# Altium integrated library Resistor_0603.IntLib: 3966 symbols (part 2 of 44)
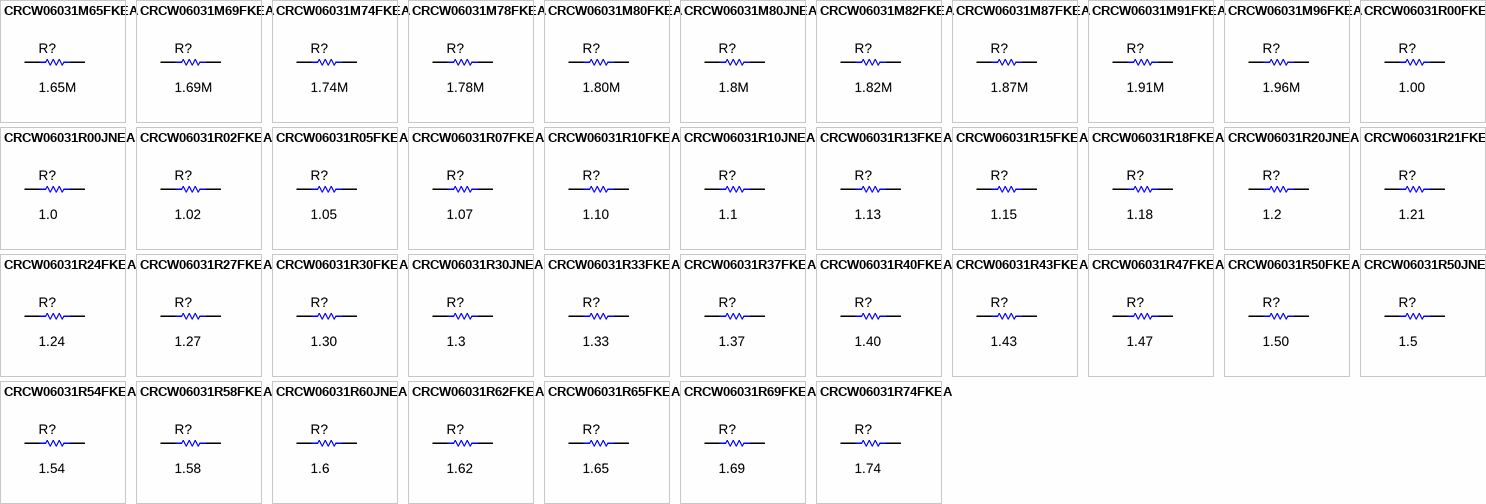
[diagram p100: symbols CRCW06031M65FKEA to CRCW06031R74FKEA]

## CRCW06031M87FKEA
designator R?  ValueDisplayed: 1.87M  (hidden comment: CRCW06031M87FKEA)
RES, 1.87 M, 1%, 0.1 W, 0603; Manufacturer: Vishay-Dale; CompType: Resistor; Value: 1.87Meg; Res_ohm: 1870000; Value_Code: 1M87; Tolerance_%: 1; Power_W: 0.1; Value2: 0.1W; VDC_V: 75; TempCo: 100 ppm/C; SizeArea_mm2: 1.28; SizeX_mm: 1.6; SizeY_mm: 0.8; EIA_Code: E96; U/M: EA; AEC Category: Q200
signal-integrity model Resistor
simulation model Resistor
footprint 0603
footprint 0603M
footprint 0603L
footprint 0603_HV
footprint 0603S
pins: 1, 2

## CRCW06031M91FKEA
designator R?  ValueDisplayed: 1.91M  (hidden comment: CRCW06031M91FKEA)
RES, 1.91 M, 1%, 0.1 W, 0603; Manufacturer: Vishay-Dale; CompType: Resistor; Value: 1.91Meg; Res_ohm: 1910000; Value_Code: 1M91; Tolerance_%: 1; Power_W: 0.1; Value2: 0.1W; VDC_V: 75; TempCo: 100 ppm/C; SizeArea_mm2: 1.28; SizeX_mm: 1.6; SizeY_mm: 0.8; EIA_Code: E96; U/M: EA; AEC Category: Q200
signal-integrity model Resistor
simulation model Resistor
footprint 0603
footprint 0603M
footprint 0603L
footprint 0603_HV
footprint 0603S
pins: 1, 2

## CRCW06031M96FKEA
designator R?  ValueDisplayed: 1.96M  (hidden comment: CRCW06031M96FKEA)
RES, 1.96 M, 1%, 0.1 W, 0603; Manufacturer: Vishay-Dale; CompType: Resistor; Value: 1.96Meg; Res_ohm: 1960000; Value_Code: 1M96; Tolerance_%: 1; Power_W: 0.1; Value2: 0.1W; VDC_V: 75; TempCo: 100 ppm/C; SizeArea_mm2: 1.28; SizeX_mm: 1.6; SizeY_mm: 0.8; EIA_Code: E96; U/M: EA; AEC Category: Q200
signal-integrity model Resistor
simulation model Resistor
footprint 0603
footprint 0603M
footprint 0603L
footprint 0603_HV
footprint 0603S
pins: 1, 2

## CRCW06031R00FKEA
designator R?  ValueDisplayed: 1.00  (hidden comment: CRCW06031R00FKEA)
RES, 1.00, 1%, 0.1 W, 0603; Manufacturer: Vishay-Dale; CompType: Resistor; Value: 1.00; Res_ohm: 1; Value_Code: 1R00; Power_W: 0.1; Value2: 0.1W; VDC_V: 75; TempCo: 100 ppm/C; SizeArea_mm2: 1.28; SizeX_mm: 1.6; SizeY_mm: 0.8; EIA_Code: E96; U/M: EA; AEC Category: Q200; Green_Lifecycle: Active; Green_REACh: Passed
signal-integrity model Resistor
simulation model Resistor
footprint 0603
footprint 0603M
footprint 0603L
footprint 0603_HV
footprint 0603S
pins: 1, 2

## CRCW06031R00JNEA
designator R?  ValueDisplayed: 1.0  (hidden comment: CRCW06031R00JNEA)
RES, 1.0, 5%, 0.1 W, 0603; Manufacturer: Vishay-Dale; CompType: Resistor; Value: 1.0; Res_ohm: 1; Value_Code: 1R00; Tolerance_%: 5; Power_W: 0.1; Value2: 0.1W; VDC_V: 75; TempCo: 200 ppm/C; SizeArea_mm2: 1.28; SizeX_mm: 1.6; SizeY_mm: 0.8; EIA_Code: E24; U/M: EA; AEC Category: Q200; Green_Lifecycle: Active; Green_REACh: Passed
signal-integrity model Resistor
simulation model Resistor
footprint 0603
footprint 0603M
footprint 0603L
footprint 0603_HV
footprint 0603S
pins: 1, 2

## CRCW06031R02FKEA
designator R?  ValueDisplayed: 1.02  (hidden comment: CRCW06031R02FKEA)
RES, 1.02, 1%, 0.1 W, 0603; Manufacturer: Vishay-Dale; CompType: Resistor; Value: 1.02; Value_Code: 1R02; Tolerance_%: 1; Power_W: 0.1; Value2: 0.1W; VDC_V: 75; TempCo: 100 ppm/C; SizeArea_mm2: 1.28; SizeX_mm: 1.6; SizeY_mm: 0.8; EIA_Code: E96; U/M: EA; AEC Category: Q200
signal-integrity model Resistor
simulation model Resistor
footprint 0603
footprint 0603M
footprint 0603L
footprint 0603_HV
footprint 0603S
pins: 1, 2

## CRCW06031R05FKEA
designator R?  ValueDisplayed: 1.05  (hidden comment: CRCW06031R05FKEA)
RES, 1.05, 1%, 0.1 W, 0603; Manufacturer: Vishay-Dale; CompType: Resistor; Value: 1.05; Value_Code: 1R05; Tolerance_%: 1; Power_W: 0.1; Value2: 0.1W; VDC_V: 75; TempCo: 100 ppm/C; SizeArea_mm2: 1.28; SizeX_mm: 1.6; SizeY_mm: 0.8; EIA_Code: E96; U/M: EA; AEC Category: Q200
signal-integrity model Resistor
simulation model Resistor
footprint 0603
footprint 0603M
footprint 0603L
footprint 0603_HV
footprint 0603S
pins: 1, 2

## CRCW06031R07FKEA
designator R?  ValueDisplayed: 1.07  (hidden comment: CRCW06031R07FKEA)
RES, 1.07, 1%, 0.1 W, 0603; Manufacturer: Vishay-Dale; CompType: Resistor; Value: 1.07; Value_Code: 1R07; Tolerance_%: 1; Power_W: 0.1; Value2: 0.1W; VDC_V: 75; TempCo: 100 ppm/C; SizeArea_mm2: 1.28; SizeX_mm: 1.6; SizeY_mm: 0.8; EIA_Code: E96; U/M: EA; AEC Category: Q200
signal-integrity model Resistor
simulation model Resistor
footprint 0603
footprint 0603M
footprint 0603L
footprint 0603_HV
footprint 0603S
pins: 1, 2

## CRCW06031R10FKEA
designator R?  ValueDisplayed: 1.10  (hidden comment: CRCW06031R10FKEA)
RES, 1.10, 1%, 0.1 W, 0603; Manufacturer: Vishay-Dale; CompType: Resistor; Value: 1.10; Res_ohm: 1.1; Value_Code: 1R10; Tolerance_%: 1; Power_W: 0.1; Value2: 0.1W; VDC_V: 75; TempCo: 100 ppm/C; SizeArea_mm2: 1.28; SizeX_mm: 1.6; SizeY_mm: 0.8; EIA_Code: E96; U/M: EA; AEC Category: Q200
signal-integrity model Resistor
simulation model Resistor
footprint 0603
footprint 0603M
footprint 0603L
footprint 0603_HV
footprint 0603S
pins: 1, 2

## CRCW06031R10JNEA
designator R?  ValueDisplayed: 1.1  (hidden comment: CRCW06031R10JNEA)
RES, 1.1, 5%, 0.1 W, 0603; Manufacturer: Vishay-Dale; CompType: Resistor; Value: 1.1; Value_Code: 1R10; Tolerance_%: 5; Power_W: 0.1; Value2: 0.1W; VDC_V: 75; TempCo: 200 ppm/C; SizeArea_mm2: 1.28; SizeX_mm: 1.6; SizeY_mm: 0.8; SizeZ_mm: 1; EIA_Code: E24; U/M: EA; AEC Category: Q200; Green_Lifecycle: Active; Green_REACh: Passed
signal-integrity model Resistor
simulation model Resistor
footprint 0603
footprint 0603M
footprint 0603L
footprint 0603_HV
footprint 0603S
pins: 1, 2

## CRCW06031R13FKEA
designator R?  ValueDisplayed: 1.13  (hidden comment: CRCW06031R13FKEA)
RES, 1.13, 1%, 0.1 W, 0603; Manufacturer: Vishay-Dale; CompType: Resistor; Value: 1.13; Value_Code: 1R13; Tolerance_%: 1; Power_W: 0.1; Value2: 0.1W; VDC_V: 75; TempCo: 100 ppm/C; SizeArea_mm2: 1.28; SizeX_mm: 1.6; SizeY_mm: 0.8; EIA_Code: E96; U/M: EA; AEC Category: Q200
signal-integrity model Resistor
simulation model Resistor
footprint 0603
footprint 0603M
footprint 0603L
footprint 0603_HV
footprint 0603S
pins: 1, 2

## CRCW06031R15FKEA
designator R?  ValueDisplayed: 1.15  (hidden comment: CRCW06031R15FKEA)
RES, 1.15, 1%, 0.1 W, 0603; Manufacturer: Vishay-Dale; CompType: Resistor; Value: 1.15; Value_Code: 1R15; Tolerance_%: 1; Power_W: 0.1; Value2: 0.1W; VDC_V: 75; TempCo: 100 ppm/C; SizeArea_mm2: 1.28; SizeX_mm: 1.6; SizeY_mm: 0.8; EIA_Code: E96; U/M: EA; AEC Category: Q200
signal-integrity model Resistor
simulation model Resistor
footprint 0603
footprint 0603M
footprint 0603L
footprint 0603_HV
footprint 0603S
pins: 1, 2

## CRCW06031R18FKEA
designator R?  ValueDisplayed: 1.18  (hidden comment: CRCW06031R18FKEA)
RES, 1.18, 1%, 0.1 W, 0603; Manufacturer: Vishay-Dale; CompType: Resistor; Value: 1.18; Value_Code: 1R18; Tolerance_%: 1; Power_W: 0.1; Value2: 0.1W; VDC_V: 75; TempCo: 100 ppm/C; SizeArea_mm2: 1.28; SizeX_mm: 1.6; SizeY_mm: 0.8; EIA_Code: E96; U/M: EA; AEC Category: Q200
signal-integrity model Resistor
simulation model Resistor
footprint 0603
footprint 0603M
footprint 0603L
footprint 0603_HV
footprint 0603S
pins: 1, 2

## CRCW06031R20JNEA
designator R?  ValueDisplayed: 1.2  (hidden comment: CRCW06031R20JNEA)
RES, 1.2, 5%, 0.1 W, 0603; Manufacturer: Vishay-Dale; CompType: Resistor; Value: 1.2; Value_Code: 1R20; Tolerance_%: 5; Power_W: 0.1; Value2: 0.1W; VDC_V: 75; TempCo: 200 ppm/C; SizeArea_mm2: 1.28; SizeX_mm: 1.6; SizeY_mm: 0.8; SizeZ_mm: 1; EIA_Code: E24; U/M: EA; AEC Category: Q200
signal-integrity model Resistor
simulation model Resistor
footprint 0603
footprint 0603M
footprint 0603L
footprint 0603_HV
footprint 0603S
pins: 1, 2

## CRCW06031R21FKEA
designator R?  ValueDisplayed: 1.21  (hidden comment: CRCW06031R21FKEA)
RES, 1.21, 1%, 0.1 W, 0603; Manufacturer: Vishay-Dale; CompType: Resistor; Value: 1.21; Value_Code: 1R21; Tolerance_%: 1; Power_W: 0.1; Value2: 0.1W; VDC_V: 75; TempCo: 100 ppm/C; SizeArea_mm2: 1.28; SizeX_mm: 1.6; SizeY_mm: 0.8; EIA_Code: E96; U/M: EA; AEC Category: Q200
signal-integrity model Resistor
simulation model Resistor
footprint 0603
footprint 0603M
footprint 0603L
footprint 0603_HV
footprint 0603S
pins: 1, 2

## CRCW06031R24FKEA
designator R?  ValueDisplayed: 1.24  (hidden comment: CRCW06031R24FKEA)
RES, 1.24, 1%, 0.1 W, 0603; Manufacturer: Vishay-Dale; CompType: Resistor; Value: 1.24; Value_Code: 1R24; Tolerance_%: 1; Power_W: 0.1; Value2: 0.1W; VDC_V: 75; TempCo: 100 ppm/C; SizeArea_mm2: 1.28; SizeX_mm: 1.6; SizeY_mm: 0.8; EIA_Code: E96; U/M: EA; AEC Category: Q200
signal-integrity model Resistor
simulation model Resistor
footprint 0603
footprint 0603M
footprint 0603L
footprint 0603_HV
footprint 0603S
pins: 1, 2

## CRCW06031R27FKEA
designator R?  ValueDisplayed: 1.27  (hidden comment: CRCW06031R27FKEA)
RES, 1.27, 1%, 0.1 W, 0603; Manufacturer: Vishay-Dale; CompType: Resistor; Value: 1.27; Value_Code: 1R27; Tolerance_%: 1; Power_W: 0.1; Value2: 0.1W; VDC_V: 75; TempCo: 100 ppm/C; SizeArea_mm2: 1.28; SizeX_mm: 1.6; SizeY_mm: 0.8; EIA_Code: E96; U/M: EA; AEC Category: Q200
signal-integrity model Resistor
simulation model Resistor
footprint 0603
footprint 0603M
footprint 0603L
footprint 0603_HV
footprint 0603S
pins: 1, 2

## CRCW06031R30FKEA
designator R?  ValueDisplayed: 1.30  (hidden comment: CRCW06031R30FKEA)
RES, 1.30, 1%, 0.1 W, 0603; Manufacturer: Vishay-Dale; CompType: Resistor; Value: 1.30; Res_ohm: 1.3; Value_Code: 1R30; Tolerance_%: 1; Power_W: 0.1; Value2: 0.1W; VDC_V: 75; TempCo: 100 ppm/C; SizeArea_mm2: 1.28; SizeX_mm: 1.6; SizeY_mm: 0.8; EIA_Code: E96; U/M: EA; AEC Category: Q200
signal-integrity model Resistor
simulation model Resistor
footprint 0603
footprint 0603M
footprint 0603L
footprint 0603_HV
footprint 0603S
pins: 1, 2

## CRCW06031R30JNEA
designator R?  ValueDisplayed: 1.3  (hidden comment: CRCW06031R30JNEA)
RES, 1.3, 5%, 0.1 W, 0603; Manufacturer: Vishay-Dale; CompType: Resistor; Value: 1.3; Value_Code: 1R30; Tolerance_%: 5; Power_W: 0.1; Value2: 0.1W; VDC_V: 75; TempCo: 200 ppm/C; SizeArea_mm2: 1.28; SizeX_mm: 1.6; SizeY_mm: 0.8; SizeZ_mm: 1; EIA_Code: E24; U/M: EA; AEC Category: Q200
signal-integrity model Resistor
simulation model Resistor
footprint 0603
footprint 0603M
footprint 0603L
footprint 0603_HV
footprint 0603S
pins: 1, 2

## CRCW06031R33FKEA
designator R?  ValueDisplayed: 1.33  (hidden comment: CRCW06031R33FKEA)
RES, 1.33, 1%, 0.1 W, 0603; Manufacturer: Vishay-Dale; CompType: Resistor; Value: 1.33; Value_Code: 1R33; Tolerance_%: 1; Power_W: 0.1; Value2: 0.1W; VDC_V: 75; TempCo: 100 ppm/C; SizeArea_mm2: 1.28; SizeX_mm: 1.6; SizeY_mm: 0.8; EIA_Code: E96; U/M: EA; AEC Category: Q200
signal-integrity model Resistor
simulation model Resistor
footprint 0603
footprint 0603M
footprint 0603L
footprint 0603_HV
footprint 0603S
pins: 1, 2

## CRCW06031R37FKEA
designator R?  ValueDisplayed: 1.37  (hidden comment: CRCW06031R37FKEA)
RES, 1.37, 1%, 0.1 W, 0603; Manufacturer: Vishay-Dale; CompType: Resistor; Value: 1.37; Value_Code: 1R37; Tolerance_%: 1; Power_W: 0.1; Value2: 0.1W; VDC_V: 75; TempCo: 100 ppm/C; SizeArea_mm2: 1.28; SizeX_mm: 1.6; SizeY_mm: 0.8; EIA_Code: E96; U/M: EA; AEC Category: Q200
signal-integrity model Resistor
simulation model Resistor
footprint 0603
footprint 0603M
footprint 0603L
footprint 0603_HV
footprint 0603S
pins: 1, 2

## CRCW06031R40FKEA
designator R?  ValueDisplayed: 1.40  (hidden comment: CRCW06031R40FKEA)
RES, 1.40, 1%, 0.1 W, 0603; Manufacturer: Vishay-Dale; CompType: Resistor; Value: 1.40; Res_ohm: 1.4; Value_Code: 1R40; Tolerance_%: 1; Power_W: 0.1; Value2: 0.1W; VDC_V: 75; TempCo: 100 ppm/C; SizeArea_mm2: 1.28; SizeX_mm: 1.6; SizeY_mm: 0.8; EIA_Code: E96; U/M: EA; AEC Category: Q200
signal-integrity model Resistor
simulation model Resistor
footprint 0603
footprint 0603M
footprint 0603L
footprint 0603_HV
footprint 0603S
pins: 1, 2

## CRCW06031R43FKEA
designator R?  ValueDisplayed: 1.43  (hidden comment: CRCW06031R43FKEA)
RES, 1.43, 1%, 0.1 W, 0603; Manufacturer: Vishay-Dale; CompType: Resistor; Value: 1.43; Value_Code: 1R43; Tolerance_%: 1; Power_W: 0.1; Value2: 0.1W; VDC_V: 75; TempCo: 100 ppm/C; SizeArea_mm2: 1.28; SizeX_mm: 1.6; SizeY_mm: 0.8; EIA_Code: E96; U/M: EA; AEC Category: Q200
signal-integrity model Resistor
simulation model Resistor
footprint 0603
footprint 0603M
footprint 0603L
footprint 0603_HV
footprint 0603S
pins: 1, 2

## CRCW06031R47FKEA
designator R?  ValueDisplayed: 1.47  (hidden comment: CRCW06031R47FKEA)
RES, 1.47, 1%, 0.1 W, 0603; Manufacturer: Vishay-Dale; CompType: Resistor; Value: 1.47; Value_Code: 1R47; Tolerance_%: 1; Power_W: 0.1; Value2: 0.1W; VDC_V: 75; TempCo: 100 ppm/C; SizeArea_mm2: 1.28; SizeX_mm: 1.6; SizeY_mm: 0.8; EIA_Code: E96; U/M: EA; AEC Category: Q200
signal-integrity model Resistor
simulation model Resistor
footprint 0603
footprint 0603M
footprint 0603L
footprint 0603_HV
footprint 0603S
pins: 1, 2

## CRCW06031R50FKEA
designator R?  ValueDisplayed: 1.50  (hidden comment: CRCW06031R50FKEA)
RES, 1.50, 1%, 0.1 W, 0603; Manufacturer: Vishay-Dale; CompType: Resistor; Value: 1.50; Res_ohm: 1.5; Value_Code: 1R50; Tolerance_%: 1; Power_W: 0.1; Value2: 0.1W; VDC_V: 75; TempCo: 100 ppm/C; SizeArea_mm2: 1.28; SizeX_mm: 1.6; SizeY_mm: 0.8; EIA_Code: E96; U/M: EA; AEC Category: Q200; Green_Lifecycle: Active; Green_REACh: Passed
signal-integrity model Resistor
simulation model Resistor
footprint 0603
footprint 0603M
footprint 0603L
footprint 0603_HV
footprint 0603S
pins: 1, 2

## CRCW06031R50JNEA
designator R?  ValueDisplayed: 1.5  (hidden comment: CRCW06031R50JNEA)
RES, 1.5, 5%, 0.1 W, 0603; Manufacturer: Vishay-Dale; CompType: Resistor; Value: 1.5; Value_Code: 1R50; Tolerance_%: 5; Power_W: 0.1; Value2: 0.1W; VDC_V: 75; TempCo: 200 ppm/C; SizeArea_mm2: 1.28; SizeX_mm: 1.6; SizeY_mm: 0.8; SizeZ_mm: 1; EIA_Code: E24; U/M: EA; AEC Category: Q200
signal-integrity model Resistor
simulation model Resistor
footprint 0603
footprint 0603M
footprint 0603L
footprint 0603_HV
footprint 0603S
pins: 1, 2

## CRCW06031R54FKEA
designator R?  ValueDisplayed: 1.54  (hidden comment: CRCW06031R54FKEA)
RES, 1.54, 1%, 0.1 W, 0603; Manufacturer: Vishay-Dale; CompType: Resistor; Value: 1.54; Value_Code: 1R54; Tolerance_%: 1; Power_W: 0.1; Value2: 0.1W; VDC_V: 75; TempCo: 100 ppm/C; SizeArea_mm2: 1.28; SizeX_mm: 1.6; SizeY_mm: 0.8; EIA_Code: E96; U/M: EA; AEC Category: Q200
signal-integrity model Resistor
simulation model Resistor
footprint 0603
footprint 0603M
footprint 0603L
footprint 0603_HV
footprint 0603S
pins: 1, 2

## CRCW06031R58FKEA
designator R?  ValueDisplayed: 1.58  (hidden comment: CRCW06031R58FKEA)
RES, 1.58, 1%, 0.1 W, 0603; Manufacturer: Vishay-Dale; CompType: Resistor; Value: 1.58; Value_Code: 1R58; Tolerance_%: 1; Power_W: 0.1; Value2: 0.1W; VDC_V: 75; TempCo: 100 ppm/C; SizeArea_mm2: 1.28; SizeX_mm: 1.6; SizeY_mm: 0.8; EIA_Code: E96; U/M: EA; AEC Category: Q200
signal-integrity model Resistor
simulation model Resistor
footprint 0603
footprint 0603M
footprint 0603L
footprint 0603_HV
footprint 0603S
pins: 1, 2

## CRCW06031R60JNEA
designator R?  ValueDisplayed: 1.6  (hidden comment: CRCW06031R60JNEA)
RES, 1.6, 5%, 0.1 W, 0603; Manufacturer: Vishay-Dale; CompType: Resistor; Value: 1.6; Value_Code: 1R60; Tolerance_%: 5; Power_W: 0.1; Value2: 0.1W; VDC_V: 75; TempCo: 200 ppm/C; SizeArea_mm2: 1.28; SizeY_mm: 0.8; SizeZ_mm: 1; EIA_Code: E24; U/M: EA; AEC Category: Q200
signal-integrity model Resistor
simulation model Resistor
footprint 0603
footprint 0603M
footprint 0603L
footprint 0603_HV
footprint 0603S
pins: 1, 2

## CRCW06031R62FKEA
designator R?  ValueDisplayed: 1.62  (hidden comment: CRCW06031R62FKEA)
RES, 1.62, 1%, 0.1 W, 0603; Manufacturer: Vishay-Dale; CompType: Resistor; Value: 1.62; Value_Code: 1R62; Tolerance_%: 1; Power_W: 0.1; Value2: 0.1W; VDC_V: 75; TempCo: 100 ppm/C; SizeArea_mm2: 1.28; SizeX_mm: 1.6; SizeY_mm: 0.8; EIA_Code: E96; U/M: EA; AEC Category: Q200
signal-integrity model Resistor
simulation model Resistor
footprint 0603
footprint 0603M
footprint 0603L
footprint 0603_HV
footprint 0603S
pins: 1, 2

## CRCW06031R65FKEA
designator R?  ValueDisplayed: 1.65  (hidden comment: CRCW06031R65FKEA)
RES, 1.65, 1%, 0.1 W, 0603; Manufacturer: Vishay-Dale; CompType: Resistor; Value: 1.65; Value_Code: 1R65; Tolerance_%: 1; Power_W: 0.1; Value2: 0.1W; VDC_V: 75; TempCo: 100 ppm/C; SizeArea_mm2: 1.28; SizeX_mm: 1.6; SizeY_mm: 0.8; EIA_Code: E96; U/M: EA; AEC Category: Q200
signal-integrity model Resistor
simulation model Resistor
footprint 0603
footprint 0603M
footprint 0603L
footprint 0603_HV
footprint 0603S
pins: 1, 2

## CRCW06031R69FKEA
designator R?  ValueDisplayed: 1.69  (hidden comment: CRCW06031R69FKEA)
RES, 1.69, 1%, 0.1 W, 0603; Manufacturer: Vishay-Dale; CompType: Resistor; Value: 1.69; Value_Code: 1R69; Tolerance_%: 1; Power_W: 0.1; Value2: 0.1W; VDC_V: 75; TempCo: 100 ppm/C; SizeArea_mm2: 1.28; SizeX_mm: 1.6; SizeY_mm: 0.8; EIA_Code: E96; U/M: EA; AEC Category: Q200
signal-integrity model Resistor
simulation model Resistor
footprint 0603
footprint 0603M
footprint 0603L
footprint 0603_HV
footprint 0603S
pins: 1, 2

## CRCW06031R74FKEA
designator R?  ValueDisplayed: 1.74  (hidden comment: CRCW06031R74FKEA)
RES, 1.74, 1%, 0.1 W, 0603; Manufacturer: Vishay-Dale; CompType: Resistor; Value: 1.74; Value_Code: 1R74; Tolerance_%: 1; Power_W: 0.1; Value2: 0.1W; VDC_V: 75; TempCo: 100 ppm/C; SizeArea_mm2: 1.28; SizeX_mm: 1.6; SizeY_mm: 0.8; EIA_Code: E96; U/M: EA; AEC Category: Q200
signal-integrity model Resistor
simulation model Resistor
footprint 0603
footprint 0603M
footprint 0603L
footprint 0603_HV
footprint 0603S
pins: 1, 2

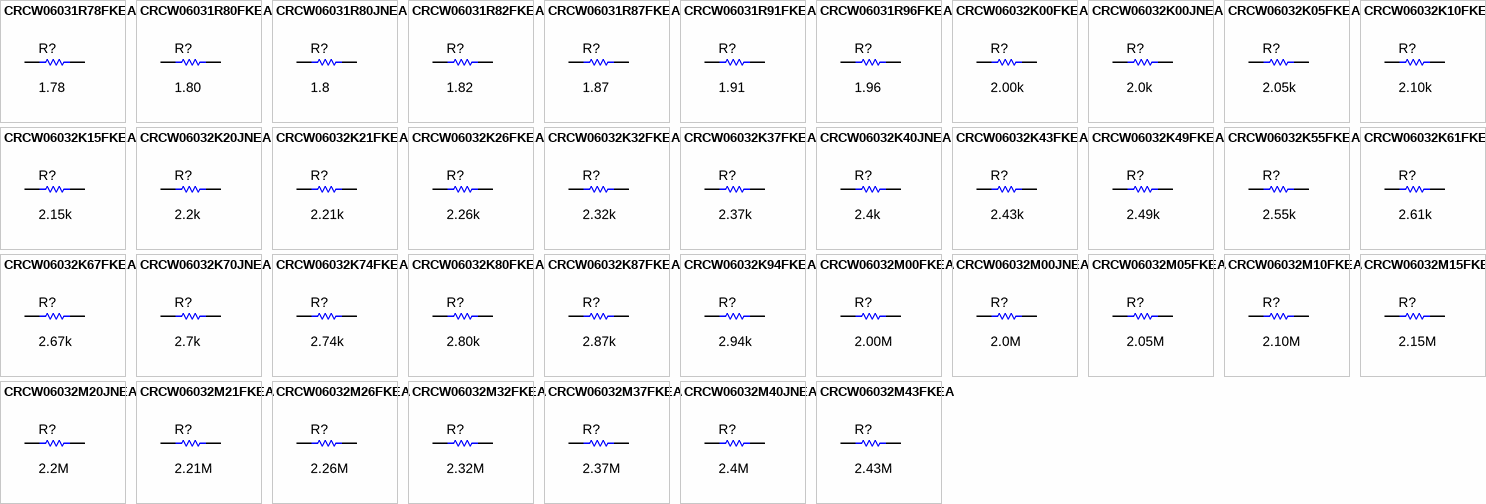
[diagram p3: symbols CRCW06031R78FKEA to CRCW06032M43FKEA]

## CRCW06031R78FKEA
designator R?  ValueDisplayed: 1.78  (hidden comment: CRCW06031R78FKEA)
RES, 1.78, 1%, 0.1 W, 0603; Manufacturer: Vishay-Dale; CompType: Resistor; Value: 1.78; Value_Code: 1R78; Tolerance_%: 1; Power_W: 0.1; Value2: 0.1W; VDC_V: 75; TempCo: 100 ppm/C; SizeArea_mm2: 1.28; SizeX_mm: 1.6; SizeY_mm: 0.8; EIA_Code: E96; U/M: EA; AEC Category: Q200
signal-integrity model Resistor
simulation model Resistor
footprint 0603
footprint 0603M
footprint 0603L
footprint 0603_HV
footprint 0603S
pins: 1, 2

## CRCW06031R80FKEA
designator R?  ValueDisplayed: 1.80  (hidden comment: CRCW06031R80FKEA)
RES, 1.80, 1%, 0.1 W, AEC-Q200 Grade 0, 0603; Manufacturer: Vishay-Dale; CompType: Resistor; Value: 1.80; Res_ohm: 1.8; Value_Code: 1R80; Tolerance_%: 1; Power_W: 0.1; Value2: 0.1W; TempCo: 100 ppm/C; SizeArea_mm2: 1.28; SizeX_mm: 1.6; SizeY_mm: 0.8; U/M: EA; AEC Category: Q200; AEC Qualified: Y; AEC Grade: 0
signal-integrity model Resistor
simulation model Resistor
footprint 0603
footprint 0603M
footprint 0603L
footprint 0603_HV
footprint 0603S
pins: 1, 2

## CRCW06031R80JNEA
designator R?  ValueDisplayed: 1.8  (hidden comment: CRCW06031R80JNEA)
RES, 1.8, 5%, 0.1 W, 0603; Manufacturer: Vishay-Dale; CompType: Resistor; Value: 1.8; Value_Code: 1R80; Tolerance_%: 5; Power_W: 0.1; Value2: 0.1W; VDC_V: 75; TempCo: 200 ppm/C; SizeArea_mm2: 1.28; SizeX_mm: 1.6; SizeY_mm: 0.8; SizeZ_mm: 1; EIA_Code: E24; U/M: EA; AEC Category: Q200
signal-integrity model Resistor
simulation model Resistor
footprint 0603
footprint 0603M
footprint 0603L
footprint 0603_HV
footprint 0603S
pins: 1, 2

## CRCW06031R82FKEA
designator R?  ValueDisplayed: 1.82  (hidden comment: CRCW06031R82FKEA)
RES, 1.82, 1%, 0.1 W, 0603; Manufacturer: Vishay-Dale; CompType: Resistor; Value: 1.82; Value_Code: 1R82; Tolerance_%: 1; Power_W: 0.1; Value2: 0.1W; VDC_V: 75; TempCo: 100 ppm/C; SizeArea_mm2: 1.28; SizeX_mm: 1.6; SizeY_mm: 0.8; EIA_Code: E96; U/M: EA; AEC Category: Q200
signal-integrity model Resistor
simulation model Resistor
footprint 0603
footprint 0603M
footprint 0603L
footprint 0603_HV
footprint 0603S
pins: 1, 2

## CRCW06031R87FKEA
designator R?  ValueDisplayed: 1.87  (hidden comment: CRCW06031R87FKEA)
RES, 1.87, 1%, 0.1 W, 0603; Manufacturer: Vishay-Dale; CompType: Resistor; Value: 1.87; Value_Code: 1R87; Tolerance_%: 1; Power_W: 0.1; Value2: 0.1W; VDC_V: 75; TempCo: 100 ppm/C; SizeArea_mm2: 1.28; SizeX_mm: 1.6; SizeY_mm: 0.8; EIA_Code: E96; U/M: EA; AEC Category: Q200
signal-integrity model Resistor
simulation model Resistor
footprint 0603
footprint 0603M
footprint 0603L
footprint 0603_HV
footprint 0603S
pins: 1, 2

## CRCW06031R91FKEA
designator R?  ValueDisplayed: 1.91  (hidden comment: CRCW06031R91FKEA)
RES, 1.91, 1%, 0.1 W, 0603; Manufacturer: Vishay-Dale; CompType: Resistor; Value: 1.91; Value_Code: 1R91; Tolerance_%: 1; Power_W: 0.1; Value2: 0.1W; VDC_V: 75; TempCo: 100 ppm/C; SizeArea_mm2: 1.28; SizeX_mm: 1.6; SizeY_mm: 0.8; EIA_Code: E96; U/M: EA; AEC Category: Q200
signal-integrity model Resistor
simulation model Resistor
footprint 0603
footprint 0603M
footprint 0603L
footprint 0603_HV
footprint 0603S
pins: 1, 2

## CRCW06031R96FKEA
designator R?  ValueDisplayed: 1.96  (hidden comment: CRCW06031R96FKEA)
RES, 1.96, 1%, 0.1 W, 0603; Manufacturer: Vishay-Dale; CompType: Resistor; Value: 1.96; Value_Code: 1R96; Tolerance_%: 1; Power_W: 0.1; Value2: 0.1W; VDC_V: 75; TempCo: 100 ppm/C; SizeArea_mm2: 1.28; SizeX_mm: 1.6; SizeY_mm: 0.8; EIA_Code: E96; U/M: EA; AEC Category: Q200
signal-integrity model Resistor
simulation model Resistor
footprint 0603
footprint 0603M
footprint 0603L
footprint 0603_HV
footprint 0603S
pins: 1, 2

## CRCW06032K00FKEA
designator R?  ValueDisplayed: 2.00k  (hidden comment: CRCW06032K00FKEA)
RES, 2.00 k, 1%, 0.1 W, 0603; Manufacturer: Vishay-Dale; CompType: Resistor; Value: 2.00k; Res_ohm: 2000; Value_Code: 2k00; Tolerance_%: 1; Power_W: 0.1; Value2: 0.1W; VDC_V: 75; TempCo: 100 ppm/C; SizeArea_mm2: 1.28; SizeX_mm: 1.6; SizeY_mm: 0.8; EIA_Code: E96; U/M: EA; AEC Category: Q200; Green_Lifecycle: Active; Green_REACh: Passed
signal-integrity model Resistor
simulation model Resistor
footprint 0603
footprint 0603M
footprint 0603L
footprint 0603_HV
footprint 0603S
pins: 1, 2

## CRCW06032K00JNEA
designator R?  ValueDisplayed: 2.0k  (hidden comment: CRCW06032K00JNEA)
RES, 2.0 k, 5%, 0.1 W, 0603; Manufacturer: Vishay-Dale; CompType: Resistor; Value: 2.0k; Res_ohm: 2000; Value_Code: 2k00; Tolerance_%: 5; Power_W: 0.1; Value2: 0.1W; VDC_V: 75; TempCo: 200 ppm/C; SizeArea_mm2: 1.28; SizeX_mm: 1.6; SizeY_mm: 0.8; SizeZ_mm: 1; EIA_Code: E24; U/M: EA; AEC Category: Q200; Green_Lifecycle: Active; Green_REACh: Passed
signal-integrity model Resistor
simulation model Resistor
footprint 0603
footprint 0603M
footprint 0603L
footprint 0603_HV
footprint 0603S
pins: 1, 2

## CRCW06032K05FKEA
designator R?  ValueDisplayed: 2.05k  (hidden comment: CRCW06032K05FKEA)
RES, 2.05 k, 1%, 0.1 W, 0603; Manufacturer: Vishay-Dale; CompType: Resistor; Value: 2.05k; Res_ohm: 2050; Value_Code: 2k05; Tolerance_%: 1; Power_W: 0.1; Value2: 0.1W; VDC_V: 75; TempCo: 100 ppm/C; SizeArea_mm2: 1.28; SizeX_mm: 1.6; SizeY_mm: 0.8; EIA_Code: E96; U/M: EA; AEC Category: Q200; Green_Lifecycle: Active; Green_REACh: Passed
signal-integrity model Resistor
simulation model Resistor
footprint 0603
footprint 0603M
footprint 0603L
footprint 0603_HV
footprint 0603S
pins: 1, 2

## CRCW06032K10FKEA
designator R?  ValueDisplayed: 2.10k  (hidden comment: CRCW06032K10FKEA)
RES, 2.10 k, 1%, 0.1 W, 0603; Manufacturer: Vishay-Dale; CompType: Resistor; Value: 2.10k; Res_ohm: 2100; Value_Code: 2k10; Tolerance_%: 1; Power_W: 0.1; Value2: 0.1W; VDC_V: 75; TempCo: 100 ppm/C; SizeArea_mm2: 1.28; SizeX_mm: 1.6; SizeY_mm: 0.8; EIA_Code: E96; U/M: EA; AEC Category: Q200; Green_Lifecycle: Active; Green_REACh: Passed
signal-integrity model Resistor
simulation model Resistor
footprint 0603
footprint 0603M
footprint 0603L
footprint 0603_HV
footprint 0603S
pins: 1, 2

## CRCW06032K15FKEA
designator R?  ValueDisplayed: 2.15k  (hidden comment: CRCW06032K15FKEA)
RES, 2.15 k, 1%, 0.1 W, 0603; Manufacturer: Vishay-Dale; CompType: Resistor; Value: 2.15k; Res_ohm: 2150; Value_Code: 2k15; Tolerance_%: 1; Power_W: 0.1; Value2: 0.1W; VDC_V: 75; TempCo: 100 ppm/C; SizeArea_mm2: 1.28; SizeX_mm: 1.6; SizeY_mm: 0.8; EIA_Code: E96; U/M: EA; AEC Category: Q200; Green_Lifecycle: Active; Green_REACh: Passed
signal-integrity model Resistor
simulation model Resistor
footprint 0603
footprint 0603M
footprint 0603L
footprint 0603_HV
footprint 0603S
pins: 1, 2

## CRCW06032K20JNEA
designator R?  ValueDisplayed: 2.2k  (hidden comment: CRCW06032K20JNEA)
RES, 2.2 k, 5%, 0.1 W, 0603; Manufacturer: Vishay-Dale; CompType: Resistor; Value: 2.2k; Res_ohm: 2200; Value_Code: 2k20; Tolerance_%: 5; Power_W: 0.1; Value2: 0.1W; VDC_V: 75; TempCo: 200 ppm/C; SizeArea_mm2: 1.28; SizeX_mm: 1.6; SizeY_mm: 0.8; SizeZ_mm: 1; EIA_Code: E24; U/M: EA; AEC Category: Q200; Green_Lifecycle: Active; Green_REACh: Passed
signal-integrity model Resistor
simulation model Resistor
footprint 0603
footprint 0603M
footprint 0603L
footprint 0603_HV
footprint 0603S
pins: 1, 2

## CRCW06032K21FKEA
designator R?  ValueDisplayed: 2.21k  (hidden comment: CRCW06032K21FKEA)
RES, 2.21 k, 1%, 0.1 W, 0603; Manufacturer: Vishay-Dale; CompType: Resistor; Value: 2.21k; Res_ohm: 2210; Value_Code: 2k21; Tolerance_%: 1; Power_W: 0.1; Value2: 0.1W; VDC_V: 75; TempCo: 100 ppm/C; SizeArea_mm2: 1.28; SizeX_mm: 1.6; SizeY_mm: 0.8; EIA_Code: E96; U/M: EA; AEC Category: Q200; Green_Lifecycle: Active; Green_REACh: Passed
signal-integrity model Resistor
simulation model Resistor
footprint 0603
footprint 0603M
footprint 0603L
footprint 0603_HV
footprint 0603S
pins: 1, 2

## CRCW06032K26FKEA
designator R?  ValueDisplayed: 2.26k  (hidden comment: CRCW06032K26FKEA)
RES, 2.26 k, 1%, 0.1 W, 0603; Manufacturer: Vishay-Dale; CompType: Resistor; Value: 2.26k; Res_ohm: 2260; Value_Code: 2k26; Tolerance_%: 1; Power_W: 0.1; Value2: 0.1W; VDC_V: 75; TempCo: 100 ppm/C; SizeArea_mm2: 1.28; SizeX_mm: 1.6; SizeY_mm: 0.8; EIA_Code: E96; U/M: EA; AEC Category: Q200; Green_Lifecycle: Active; Green_REACh: Passed
signal-integrity model Resistor
simulation model Resistor
footprint 0603
footprint 0603M
footprint 0603L
footprint 0603_HV
footprint 0603S
pins: 1, 2

## CRCW06032K32FKEA
designator R?  ValueDisplayed: 2.32k  (hidden comment: CRCW06032K32FKEA)
RES, 2.32 k, 1%, 0.1 W, 0603; Manufacturer: Vishay-Dale; CompType: Resistor; Value: 2.32k; Res_ohm: 2320; Value_Code: 2k32; Tolerance_%: 1; Power_W: 0.1; Value2: 0.1W; VDC_V: 75; TempCo: 100 ppm/C; SizeArea_mm2: 1.28; SizeX_mm: 1.6; SizeY_mm: 0.8; EIA_Code: E96; U/M: EA; AEC Category: Q200; Green_Lifecycle: Active; Green_REACh: Passed
signal-integrity model Resistor
simulation model Resistor
footprint 0603
footprint 0603M
footprint 0603L
footprint 0603_HV
footprint 0603S
pins: 1, 2

## CRCW06032K37FKEA
designator R?  ValueDisplayed: 2.37k  (hidden comment: CRCW06032K37FKEA)
RES, 2.37 k, 1%, 0.1 W, 0603; Manufacturer: Vishay-Dale; CompType: Resistor; Value: 2.37k; Res_ohm: 2370; Value_Code: 2k37; Tolerance_%: 1; Power_W: 0.1; Value2: 0.1W; VDC_V: 75; TempCo: 100 ppm/C; SizeArea_mm2: 1.28; SizeX_mm: 1.6; SizeY_mm: 0.8; EIA_Code: E96; U/M: EA; AEC Category: Q200
signal-integrity model Resistor
simulation model Resistor
footprint 0603
footprint 0603M
footprint 0603L
footprint 0603_HV
footprint 0603S
pins: 1, 2

## CRCW06032K40JNEA
designator R?  ValueDisplayed: 2.4k  (hidden comment: CRCW06032K40JNEA)
RES, 2.4 k, 5%, 0.1 W, 0603; Manufacturer: Vishay-Dale; CompType: Resistor; Value: 2.4k; Res_ohm: 2400; Value_Code: 2k40; Tolerance_%: 5; Power_W: 0.1; Value2: 0.1W; VDC_V: 75; TempCo: 200 ppm/C; SizeArea_mm2: 1.28; SizeX_mm: 1.6; SizeY_mm: 0.8; SizeZ_mm: 1; EIA_Code: E24; U/M: EA; AEC Category: Q200; Green_Lifecycle: Active; Green_REACh: Passed
signal-integrity model Resistor
simulation model Resistor
footprint 0603
footprint 0603M
footprint 0603L
footprint 0603_HV
footprint 0603S
pins: 1, 2

## CRCW06032K43FKEA
designator R?  ValueDisplayed: 2.43k  (hidden comment: CRCW06032K43FKEA)
RES, 2.43 k, 1%, 0.1 W, 0603; Manufacturer: Vishay-Dale; CompType: Resistor; Value: 2.43k; Res_ohm: 2430; Value_Code: 2k43; Tolerance_%: 1; Power_W: 0.1; Value2: 0.1W; VDC_V: 75; TempCo: 100 ppm/C; SizeArea_mm2: 1.28; SizeX_mm: 1.6; SizeY_mm: 0.8; EIA_Code: E96; U/M: EA; AEC Category: Q200
signal-integrity model Resistor
simulation model Resistor
footprint 0603
footprint 0603M
footprint 0603L
footprint 0603_HV
footprint 0603S
pins: 1, 2

## CRCW06032K49FKEA
designator R?  ValueDisplayed: 2.49k  (hidden comment: CRCW06032K49FKEA)
RES, 2.49 k, 1%, 0.1 W, 0603; Manufacturer: Vishay-Dale; CompType: Resistor; Value: 2.49k; Res_ohm: 2490; Value_Code: 2k49; Tolerance_%: 1; Power_W: 0.1; Value2: 0.1W; VDC_V: 75; TempCo: 100 ppm/C; SizeArea_mm2: 1.28; SizeX_mm: 1.6; SizeY_mm: 0.8; EIA_Code: E96; U/M: EA; AEC Category: Q200; Green_Lifecycle: Active; Green_REACh: Passed
signal-integrity model Resistor
simulation model Resistor
footprint 0603
footprint 0603M
footprint 0603L
footprint 0603_HV
footprint 0603S
pins: 1, 2

## CRCW06032K55FKEA
designator R?  ValueDisplayed: 2.55k  (hidden comment: CRCW06032K55FKEA)
RES, 2.55 k, 1%, 0.1 W, 0603; Manufacturer: Vishay-Dale; CompType: Resistor; Value: 2.55k; Res_ohm: 2550; Value_Code: 2k55; Tolerance_%: 1; Power_W: 0.1; Value2: 0.1W; VDC_V: 75; TempCo: 100 ppm/C; SizeArea_mm2: 1.28; SizeX_mm: 1.6; SizeY_mm: 0.8; EIA_Code: E96; U/M: EA; AEC Category: Q200; Green_Lifecycle: Active; Green_REACh: Passed
signal-integrity model Resistor
simulation model Resistor
footprint 0603
footprint 0603M
footprint 0603L
footprint 0603_HV
footprint 0603S
pins: 1, 2

## CRCW06032K61FKEA
designator R?  ValueDisplayed: 2.61k  (hidden comment: CRCW06032K61FKEA)
RES, 2.61 k, 1%, 0.1 W, 0603; Manufacturer: Vishay-Dale; CompType: Resistor; Value: 2.61k; Res_ohm: 2610; Value_Code: 2k61; Tolerance_%: 1; Power_W: 0.1; Value2: 0.1W; VDC_V: 75; TempCo: 100 ppm/C; SizeArea_mm2: 1.28; SizeX_mm: 1.6; SizeY_mm: 0.8; EIA_Code: E96; U/M: EA; AEC Category: Q200; Green_Lifecycle: Active; Green_REACh: Passed
signal-integrity model Resistor
simulation model Resistor
footprint 0603
footprint 0603M
footprint 0603L
footprint 0603_HV
footprint 0603S
pins: 1, 2

## CRCW06032K67FKEA
designator R?  ValueDisplayed: 2.67k  (hidden comment: CRCW06032K67FKEA)
RES, 2.67 k, 1%, 0.1 W, 0603; Manufacturer: Vishay-Dale; CompType: Resistor; Value: 2.67k; Res_ohm: 2670; Value_Code: 2k67; Tolerance_%: 1; Power_W: 0.1; Value2: 0.1W; VDC_V: 75; TempCo: 100 ppm/C; SizeArea_mm2: 1.28; SizeX_mm: 1.6; SizeY_mm: 0.8; EIA_Code: E96; U/M: EA; AEC Category: Q200; Green_Lifecycle: Active; Green_REACh: Passed
signal-integrity model Resistor
simulation model Resistor
footprint 0603
footprint 0603M
footprint 0603L
footprint 0603_HV
footprint 0603S
pins: 1, 2

## CRCW06032K70JNEA
designator R?  ValueDisplayed: 2.7k  (hidden comment: CRCW06032K70JNEA)
RES, 2.7 k, 5%, 0.1 W, 0603; Manufacturer: Vishay-Dale; CompType: Resistor; Value: 2.7k; Res_ohm: 2700; Value_Code: 2k70; Tolerance_%: 5; Power_W: 0.1; Value2: 0.1W; VDC_V: 75; TempCo: 200 ppm/C; SizeArea_mm2: 1.28; SizeX_mm: 1.6; SizeY_mm: 0.8; SizeZ_mm: 1; EIA_Code: E24; U/M: EA; AEC Category: Q200; Green_Lifecycle: Active; Green_REACh: Passed
signal-integrity model Resistor
simulation model Resistor
footprint 0603
footprint 0603M
footprint 0603L
footprint 0603_HV
footprint 0603S
pins: 1, 2

## CRCW06032K74FKEA
designator R?  ValueDisplayed: 2.74k  (hidden comment: CRCW06032K74FKEA)
RES, 2.74 k, 1%, 0.1 W, 0603; Manufacturer: Vishay-Dale; CompType: Resistor; Value: 2.74k; Res_ohm: 2740; Value_Code: 2k74; Tolerance_%: 1; Power_W: 0.1; Value2: 0.1W; VDC_V: 75; TempCo: 100 ppm/C; SizeArea_mm2: 1.28; SizeX_mm: 1.6; SizeY_mm: 0.8; EIA_Code: E96; U/M: EA; AEC Category: Q200; Green_Lifecycle: Active; Green_REACh: Passed
signal-integrity model Resistor
simulation model Resistor
footprint 0603
footprint 0603M
footprint 0603L
footprint 0603_HV
footprint 0603S
pins: 1, 2

## CRCW06032K80FKEA
designator R?  ValueDisplayed: 2.80k  (hidden comment: CRCW06032K80FKEA)
RES, 2.80 k, 1%, 0.1 W, 0603; Manufacturer: Vishay-Dale; CompType: Resistor; Value: 2.80k; Res_ohm: 2800; Value_Code: 2k80; Tolerance_%: 1; Power_W: 0.1; Value2: 0.1W; VDC_V: 75; TempCo: 100 ppm/C; SizeArea_mm2: 1.28; SizeX_mm: 1.6; SizeY_mm: 0.8; EIA_Code: E96; U/M: EA; AEC Category: Q200; Green_Lifecycle: Active; Green_REACh: Passed
signal-integrity model Resistor
simulation model Resistor
footprint 0603
footprint 0603M
footprint 0603L
footprint 0603_HV
footprint 0603S
pins: 1, 2

## CRCW06032K87FKEA
designator R?  ValueDisplayed: 2.87k  (hidden comment: CRCW06032K87FKEA)
RES, 2.87 k, 1%, 0.1 W, 0603; Manufacturer: Vishay-Dale; CompType: Resistor; Value: 2.87k; Res_ohm: 2870; Value_Code: 2k87; Tolerance_%: 1; Power_W: 0.1; Value2: 0.1W; VDC_V: 75; TempCo: 100 ppm/C; SizeArea_mm2: 1.28; SizeX_mm: 1.6; SizeY_mm: 0.8; EIA_Code: E96; U/M: EA; AEC Category: Q200; Green_Lifecycle: Active; Green_REACh: Passed
signal-integrity model Resistor
simulation model Resistor
footprint 0603
footprint 0603M
footprint 0603L
footprint 0603_HV
footprint 0603S
pins: 1, 2

## CRCW06032K94FKEA
designator R?  ValueDisplayed: 2.94k  (hidden comment: CRCW06032K94FKEA)
RES, 2.94 k, 1%, 0.1 W, 0603; Manufacturer: Vishay-Dale; CompType: Resistor; Value: 2.94k; Res_ohm: 2940; Value_Code: 2k94; Tolerance_%: 1; Power_W: 0.1; Value2: 0.1W; VDC_V: 75; TempCo: 100 ppm/C; SizeArea_mm2: 1.28; SizeX_mm: 1.6; SizeY_mm: 0.8; EIA_Code: E96; U/M: EA; AEC Category: Q200
signal-integrity model Resistor
simulation model Resistor
footprint 0603
footprint 0603M
footprint 0603L
footprint 0603_HV
footprint 0603S
pins: 1, 2

## CRCW06032M00FKEA
designator R?  ValueDisplayed: 2.00M  (hidden comment: CRCW06032M00FKEA)
RES, 2.00 M, 1%, 0.1 W, 0603; Manufacturer: Vishay-Dale; CompType: Resistor; Value: 2.00Meg; Res_ohm: 2000000; Value_Code: 2M00; Tolerance_%: 1; Power_W: 0.1; Value2: 0.1W; VDC_V: 75; TempCo: 100 ppm/C; SizeArea_mm2: 1.28; SizeX_mm: 1.6; SizeY_mm: 0.8; EIA_Code: E96; U/M: EA; AEC Category: Q200; Green_Lifecycle: Active; Green_REACh: Passed
signal-integrity model Resistor
simulation model Resistor
footprint 0603
footprint 0603M
footprint 0603L
footprint 0603_HV
footprint 0603S
pins: 1, 2

## CRCW06032M00JNEA
designator R?  ValueDisplayed: 2.0M  (hidden comment: CRCW06032M00JNEA)
RES, 2.0 M, 5%, 0.1 W, 0603; Manufacturer: Vishay-Dale; CompType: Resistor; Value: 2.0Meg; Res_ohm: 2000000; Value_Code: 2M00; Tolerance_%: 5; Power_W: 0.1; Value2: 0.1W; VDC_V: 75; TempCo: 200 ppm/C; SizeArea_mm2: 1.28; SizeX_mm: 1.6; SizeY_mm: 0.8; SizeZ_mm: 1; EIA_Code: E24; U/M: EA; AEC Category: Q200
signal-integrity model Resistor
simulation model Resistor
footprint 0603
footprint 0603M
footprint 0603L
footprint 0603_HV
footprint 0603S
pins: 1, 2

## CRCW06032M05FKEA
designator R?  ValueDisplayed: 2.05M  (hidden comment: CRCW06032M05FKEA)
RES, 2.05 M, 1%, 0.1 W, 0603; Manufacturer: Vishay-Dale; CompType: Resistor; Value: 2.05Meg; Res_ohm: 2050000; Value_Code: 2M05; Tolerance_%: 1; Power_W: 0.1; Value2: 0.1W; VDC_V: 75; TempCo: 100 ppm/C; SizeArea_mm2: 1.28; SizeX_mm: 1.6; SizeY_mm: 0.8; EIA_Code: E96; U/M: EA; AEC Category: Q200
signal-integrity model Resistor
simulation model Resistor
footprint 0603
footprint 0603M
footprint 0603L
footprint 0603_HV
footprint 0603S
pins: 1, 2

## CRCW06032M10FKEA
designator R?  ValueDisplayed: 2.10M  (hidden comment: CRCW06032M10FKEA)
RES, 2.10 M, 1%, 0.1 W, 0603; Manufacturer: Vishay-Dale; CompType: Resistor; Value: 2.10Meg; Res_ohm: 2100000; Value_Code: 2M10; Tolerance_%: 1; Power_W: 0.1; Value2: 0.1W; VDC_V: 75; TempCo: 100 ppm/C; SizeArea_mm2: 1.28; SizeX_mm: 1.6; SizeY_mm: 0.8; EIA_Code: E96; U/M: EA; AEC Category: Q200
signal-integrity model Resistor
simulation model Resistor
footprint 0603
footprint 0603M
footprint 0603L
footprint 0603_HV
footprint 0603S
pins: 1, 2

## CRCW06032M15FKEA
designator R?  ValueDisplayed: 2.15M  (hidden comment: CRCW06032M15FKEA)
RES, 2.15 M, 1%, 0.1 W, 0603; Manufacturer: Vishay-Dale; CompType: Resistor; Value: 2.15Meg; Res_ohm: 2150000; Value_Code: 2M15; Tolerance_%: 1; Power_W: 0.1; Value2: 0.1W; VDC_V: 75; TempCo: 100 ppm/C; SizeArea_mm2: 1.28; SizeX_mm: 1.6; SizeY_mm: 0.8; EIA_Code: E96; U/M: EA; AEC Category: Q200
signal-integrity model Resistor
simulation model Resistor
footprint 0603
footprint 0603M
footprint 0603L
footprint 0603_HV
footprint 0603S
pins: 1, 2

## CRCW06032M20JNEA
designator R?  ValueDisplayed: 2.2M  (hidden comment: CRCW06032M20JNEA)
RES, 2.2 M, 5%, 0.1 W, 0603; Manufacturer: Vishay-Dale; CompType: Resistor; Value: 2.2Meg; Res_ohm: 2200000; Value_Code: 2M20; Tolerance_%: 5; Power_W: 0.1; Value2: 0.1W; VDC_V: 75; TempCo: 200 ppm/C; SizeArea_mm2: 1.28; SizeX_mm: 1.6; SizeY_mm: 0.8; SizeZ_mm: 1; EIA_Code: E24; U/M: EA; AEC Category: Q200
signal-integrity model Resistor
simulation model Resistor
footprint 0603
footprint 0603M
footprint 0603L
footprint 0603_HV
footprint 0603S
pins: 1, 2

## CRCW06032M21FKEA
designator R?  ValueDisplayed: 2.21M  (hidden comment: CRCW06032M21FKEA)
RES, 2.21 M, 1%, 0.1 W, 0603; Manufacturer: Vishay-Dale; CompType: Resistor; Value: 2.21Meg; Res_ohm: 2210000; Value_Code: 2M21; Tolerance_%: 1; Power_W: 0.1; Value2: 0.1W; VDC_V: 75; TempCo: 100 ppm/C; SizeArea_mm2: 1.28; SizeX_mm: 1.6; SizeY_mm: 0.8; EIA_Code: E96; U/M: EA; AEC Category: Q200
signal-integrity model Resistor
simulation model Resistor
footprint 0603
footprint 0603M
footprint 0603L
footprint 0603_HV
footprint 0603S
pins: 1, 2

## CRCW06032M26FKEA
designator R?  ValueDisplayed: 2.26M  (hidden comment: CRCW06032M26FKEA)
RES, 2.26 M, 1%, 0.1 W, 0603; Manufacturer: Vishay-Dale; CompType: Resistor; Value: 2.26Meg; Res_ohm: 2260000; Value_Code: 2M26; Tolerance_%: 1; Power_W: 0.1; Value2: 0.1W; VDC_V: 75; TempCo: 100 ppm/C; SizeArea_mm2: 1.28; SizeX_mm: 1.6; SizeY_mm: 0.8; EIA_Code: E96; U/M: EA; AEC Category: Q200
signal-integrity model Resistor
simulation model Resistor
footprint 0603
footprint 0603M
footprint 0603L
footprint 0603_HV
footprint 0603S
pins: 1, 2

## CRCW06032M32FKEA
designator R?  ValueDisplayed: 2.32M  (hidden comment: CRCW06032M32FKEA)
RES, 2.32 M, 1%, 0.1 W, 0603; Manufacturer: Vishay-Dale; CompType: Resistor; Value: 2.32Meg; Res_ohm: 2320000; Value_Code: 2M32; Tolerance_%: 1; Power_W: 0.1; Value2: 0.1W; VDC_V: 75; TempCo: 100 ppm/C; SizeArea_mm2: 1.28; SizeX_mm: 1.6; SizeY_mm: 0.8; EIA_Code: E96; U/M: EA; AEC Category: Q200
signal-integrity model Resistor
simulation model Resistor
footprint 0603
footprint 0603M
footprint 0603L
footprint 0603_HV
footprint 0603S
pins: 1, 2

## CRCW06032M37FKEA
designator R?  ValueDisplayed: 2.37M  (hidden comment: CRCW06032M37FKEA)
RES, 2.37 M, 1%, 0.1 W, 0603; Manufacturer: Vishay-Dale; CompType: Resistor; Value: 2.37Meg; Res_ohm: 2370000; Value_Code: 2M37; Tolerance_%: 1; Power_W: 0.1; Value2: 0.1W; VDC_V: 75; TempCo: 100 ppm/C; SizeArea_mm2: 1.28; SizeX_mm: 1.6; SizeY_mm: 0.8; EIA_Code: E96; U/M: EA; AEC Category: Q200
signal-integrity model Resistor
simulation model Resistor
footprint 0603
footprint 0603M
footprint 0603L
footprint 0603_HV
footprint 0603S
pins: 1, 2

## CRCW06032M40JNEA
designator R?  ValueDisplayed: 2.4M  (hidden comment: CRCW06032M40JNEA)
RES, 2.4 M, 5%, 0.1 W, 0603; Manufacturer: Vishay-Dale; CompType: Resistor; Value: 2.4Meg; Res_ohm: 2400000; Value_Code: 2M40; Tolerance_%: 5; Power_W: 0.1; Value2: 0.1W; VDC_V: 75; TempCo: 200 ppm/C; SizeArea_mm2: 1.28; SizeX_mm: 1.6; SizeY_mm: 0.8; SizeZ_mm: 1; EIA_Code: E24; U/M: EA; AEC Category: Q200
signal-integrity model Resistor
simulation model Resistor
footprint 0603
footprint 0603M
footprint 0603L
footprint 0603_HV
footprint 0603S
pins: 1, 2

## CRCW06032M43FKEA
designator R?  ValueDisplayed: 2.43M  (hidden comment: CRCW06032M43FKEA)
RES, 2.43 M, 1%, 0.1 W, 0603; Manufacturer: Vishay-Dale; CompType: Resistor; Value: 2.43Meg; Res_ohm: 2430000; Value_Code: 2M43; Tolerance_%: 1; Power_W: 0.1; Value2: 0.1W; VDC_V: 75; TempCo: 100 ppm/C; SizeArea_mm2: 1.28; SizeX_mm: 1.6; SizeY_mm: 0.8; EIA_Code: E96; U/M: EA; AEC Category: Q200
signal-integrity model Resistor
simulation model Resistor
footprint 0603
footprint 0603M
footprint 0603L
footprint 0603_HV
footprint 0603S
pins: 1, 2

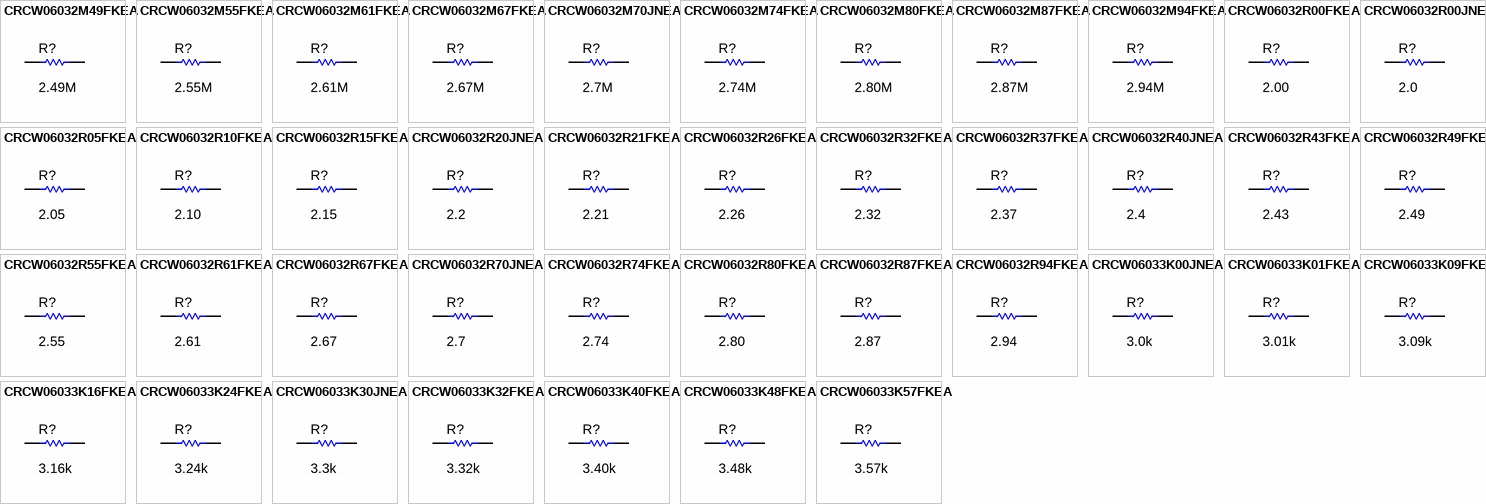
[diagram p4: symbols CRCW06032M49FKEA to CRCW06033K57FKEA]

## CRCW06032M49FKEA
designator R?  ValueDisplayed: 2.49M  (hidden comment: CRCW06032M49FKEA)
RES, 2.49 M, 1%, 0.1 W, 0603; Manufacturer: Vishay-Dale; CompType: Resistor; Value: 2.49Meg; Res_ohm: 2490000; Value_Code: 2M49; Tolerance_%: 1; Power_W: 0.1; Value2: 0.1W; VDC_V: 75; TempCo: 100 ppm/C; SizeArea_mm2: 1.28; SizeX_mm: 1.6; SizeY_mm: 0.8; EIA_Code: E96; U/M: EA; AEC Category: Q200
signal-integrity model Resistor
simulation model Resistor
footprint 0603
footprint 0603M
footprint 0603L
footprint 0603_HV
footprint 0603S
pins: 1, 2

## CRCW06032M55FKEA
designator R?  ValueDisplayed: 2.55M  (hidden comment: CRCW06032M55FKEA)
RES, 2.55 M, 1%, 0.1 W, 0603; Manufacturer: Vishay-Dale; CompType: Resistor; Value: 2.55Meg; Res_ohm: 2550000; Value_Code: 2M55; Tolerance_%: 1; Power_W: 0.1; Value2: 0.1W; VDC_V: 75; TempCo: 100 ppm/C; SizeArea_mm2: 1.28; SizeX_mm: 1.6; SizeY_mm: 0.8; EIA_Code: E96; U/M: EA; AEC Category: Q200
signal-integrity model Resistor
simulation model Resistor
footprint 0603
footprint 0603M
footprint 0603L
footprint 0603_HV
footprint 0603S
pins: 1, 2

## CRCW06032M61FKEA
designator R?  ValueDisplayed: 2.61M  (hidden comment: CRCW06032M61FKEA)
RES, 2.61 M, 1%, 0.1 W, 0603; Manufacturer: Vishay-Dale; CompType: Resistor; Value: 2.61Meg; Res_ohm: 2610000; Value_Code: 2M61; Tolerance_%: 1; Power_W: 0.1; Value2: 0.1W; VDC_V: 75; TempCo: 100 ppm/C; SizeArea_mm2: 1.28; SizeX_mm: 1.6; SizeY_mm: 0.8; EIA_Code: E96; U/M: EA; AEC Category: Q200
signal-integrity model Resistor
simulation model Resistor
footprint 0603
footprint 0603M
footprint 0603L
footprint 0603_HV
footprint 0603S
pins: 1, 2

## CRCW06032M67FKEA
designator R?  ValueDisplayed: 2.67M  (hidden comment: CRCW06032M67FKEA)
RES, 2.67 M, 1%, 0.1 W, 0603; Manufacturer: Vishay-Dale; CompType: Resistor; Value: 2.67Meg; Res_ohm: 2670000; Value_Code: 2M67; Tolerance_%: 1; Power_W: 0.1; Value2: 0.1W; VDC_V: 75; TempCo: 100 ppm/C; SizeArea_mm2: 1.28; SizeX_mm: 1.6; SizeY_mm: 0.8; EIA_Code: E96; U/M: EA; AEC Category: Q200
signal-integrity model Resistor
simulation model Resistor
footprint 0603
footprint 0603M
footprint 0603L
footprint 0603_HV
footprint 0603S
pins: 1, 2

## CRCW06032M70JNEA
designator R?  ValueDisplayed: 2.7M  (hidden comment: CRCW06032M70JNEA)
RES, 2.7 M, 5%, 0.1 W, 0603; Manufacturer: Vishay-Dale; CompType: Resistor; Value: 2.7Meg; Res_ohm: 2700000; Value_Code: 2M70; Tolerance_%: 5; Power_W: 0.1; Value2: 0.1W; VDC_V: 75; TempCo: 200 ppm/C; SizeArea_mm2: 1.28; SizeX_mm: 1.6; SizeY_mm: 0.8; SizeZ_mm: 1; EIA_Code: E24; U/M: EA; AEC Category: Q200
signal-integrity model Resistor
simulation model Resistor
footprint 0603
footprint 0603M
footprint 0603L
footprint 0603_HV
footprint 0603S
pins: 1, 2

## CRCW06032M74FKEA
designator R?  ValueDisplayed: 2.74M  (hidden comment: CRCW06032M74FKEA)
RES, 2.74 M, 1%, 0.1 W, 0603; Manufacturer: Vishay-Dale; CompType: Resistor; Value: 2.74Meg; Res_ohm: 2740000; Value_Code: 2M74; Tolerance_%: 1; Power_W: 0.1; Value2: 0.1W; VDC_V: 75; TempCo: 100 ppm/C; SizeArea_mm2: 1.28; SizeX_mm: 1.6; SizeY_mm: 0.8; EIA_Code: E96; U/M: EA; AEC Category: Q200
signal-integrity model Resistor
simulation model Resistor
footprint 0603
footprint 0603M
footprint 0603L
footprint 0603_HV
footprint 0603S
pins: 1, 2

## CRCW06032M80FKEA
designator R?  ValueDisplayed: 2.80M  (hidden comment: CRCW06032M80FKEA)
RES, 2.80 M, 1%, 0.1 W, 0603; Manufacturer: Vishay-Dale; CompType: Resistor; Value: 2.80Meg; Res_ohm: 2800000; Value_Code: 2M80; Tolerance_%: 1; Power_W: 0.1; Value2: 0.1W; VDC_V: 75; TempCo: 100 ppm/C; SizeArea_mm2: 1.28; SizeX_mm: 1.6; SizeY_mm: 0.8; EIA_Code: E96; U/M: EA; AEC Category: Q200
signal-integrity model Resistor
simulation model Resistor
footprint 0603
footprint 0603M
footprint 0603L
footprint 0603_HV
footprint 0603S
pins: 1, 2

## CRCW06032M87FKEA
designator R?  ValueDisplayed: 2.87M  (hidden comment: CRCW06032M87FKEA)
RES, 2.87 M, 1%, 0.1 W, 0603; Manufacturer: Vishay-Dale; CompType: Resistor; Value: 2.87Meg; Res_ohm: 2870000; Value_Code: 2M87; Tolerance_%: 1; Power_W: 0.1; Value2: 0.1W; VDC_V: 75; TempCo: 100 ppm/C; SizeArea_mm2: 1.28; SizeX_mm: 1.6; SizeY_mm: 0.8; EIA_Code: E96; U/M: EA; AEC Category: Q200
signal-integrity model Resistor
simulation model Resistor
footprint 0603
footprint 0603M
footprint 0603L
footprint 0603_HV
footprint 0603S
pins: 1, 2

## CRCW06032M94FKEA
designator R?  ValueDisplayed: 2.94M  (hidden comment: CRCW06032M94FKEA)
RES, 2.94 M, 1%, 0.1 W, 0603; Manufacturer: Vishay-Dale; CompType: Resistor; Value: 2.94Meg; Res_ohm: 2940000; Value_Code: 2M94; Tolerance_%: 1; Power_W: 0.1; Value2: 0.1W; VDC_V: 75; TempCo: 100 ppm/C; SizeArea_mm2: 1.28; SizeX_mm: 1.6; SizeY_mm: 0.8; EIA_Code: E96; U/M: EA; AEC Category: Q200
signal-integrity model Resistor
simulation model Resistor
footprint 0603
footprint 0603M
footprint 0603L
footprint 0603_HV
footprint 0603S
pins: 1, 2

## CRCW06032R00FKEA
designator R?  ValueDisplayed: 2.00  (hidden comment: CRCW06032R00FKEA)
RES, 2.00, 1%, 0.1 W, 0603; Manufacturer: Vishay-Dale; CompType: Resistor; Value: 2.00; Res_ohm: 2; Value_Code: 2R00; Tolerance_%: 1; Power_W: 0.1; Value2: 0.1W; VDC_V: 75; TempCo: 100 ppm/C; SizeArea_mm2: 1.28; SizeX_mm: 1.6; SizeY_mm: 0.8; EIA_Code: E96; U/M: EA; AEC Category: Q200; Green_Lifecycle: Active; Green_REACh: Passed
signal-integrity model Resistor
simulation model Resistor
footprint 0603
footprint 0603M
footprint 0603L
footprint 0603_HV
footprint 0603S
pins: 1, 2

## CRCW06032R00JNEA
designator R?  ValueDisplayed: 2.0  (hidden comment: CRCW06032R00JNEA)
RES, 2.0, 5%, 0.1 W, 0603; Manufacturer: Vishay-Dale; CompType: Resistor; Value: 2.0; Res_ohm: 2; Value_Code: 2R00; Tolerance_%: 5; Power_W: 0.1; Value2: 0.1W; VDC_V: 75; TempCo: 200 ppm/C; SizeArea_mm2: 1.28; SizeX_mm: 1.6; SizeY_mm: 0.8; SizeZ_mm: 1; EIA_Code: E24; U/M: EA; AEC Category: Q200; Green_Lifecycle: Active; Green_REACh: Passed
signal-integrity model Resistor
simulation model Resistor
footprint 0603
footprint 0603M
footprint 0603L
footprint 0603_HV
footprint 0603S
pins: 1, 2

## CRCW06032R05FKEA
designator R?  ValueDisplayed: 2.05  (hidden comment: CRCW06032R05FKEA)
RES, 2.05, 1%, 0.1 W, 0603; Manufacturer: Vishay-Dale; CompType: Resistor; Value: 2.05; Value_Code: 2R05; Tolerance_%: 1; Power_W: 0.1; Value2: 0.1W; VDC_V: 75; TempCo: 100 ppm/C; SizeArea_mm2: 1.28; SizeX_mm: 1.6; SizeY_mm: 0.8; EIA_Code: E96; U/M: EA; AEC Category: Q200; Green_Lifecycle: Active; Green_REACh: Passed
signal-integrity model Resistor
simulation model Resistor
footprint 0603
footprint 0603M
footprint 0603L
footprint 0603_HV
footprint 0603S
pins: 1, 2

## CRCW06032R10FKEA
designator R?  ValueDisplayed: 2.10  (hidden comment: CRCW06032R10FKEA)
RES, 2.10, 1%, 0.1 W, 0603; Manufacturer: Vishay-Dale; CompType: Resistor; Value: 2.10; Res_ohm: 2.1; Value_Code: 2R10; Tolerance_%: 1; Power_W: 0.1; Value2: 0.1W; VDC_V: 75; TempCo: 100 ppm/C; SizeArea_mm2: 1.28; SizeX_mm: 1.6; SizeY_mm: 0.8; EIA_Code: E96; U/M: EA; AEC Category: Q200
signal-integrity model Resistor
simulation model Resistor
footprint 0603
footprint 0603M
footprint 0603L
footprint 0603_HV
footprint 0603S
pins: 1, 2

## CRCW06032R15FKEA
designator R?  ValueDisplayed: 2.15  (hidden comment: CRCW06032R15FKEA)
RES, 2.15, 1%, 0.1 W, 0603; Manufacturer: Vishay-Dale; CompType: Resistor; Value: 2.15; Value_Code: 2R15; Tolerance_%: 1; Power_W: 0.1; Value2: 0.1W; VDC_V: 75; TempCo: 100 ppm/C; SizeArea_mm2: 1.28; SizeX_mm: 1.6; SizeY_mm: 0.8; EIA_Code: E96; U/M: EA; AEC Category: Q200
signal-integrity model Resistor
simulation model Resistor
footprint 0603
footprint 0603M
footprint 0603L
footprint 0603_HV
footprint 0603S
pins: 1, 2

## CRCW06032R20JNEA
designator R?  ValueDisplayed: 2.2  (hidden comment: CRCW06032R20JNEA)
RES, 2.2, 5%, 0.1 W, 0603; Manufacturer: Vishay-Dale; CompType: Resistor; Value: 2.2; Value_Code: 2R20; Tolerance_%: 5; Power_W: 0.1; Value2: 0.1W; VDC_V: 75; TempCo: 200 ppm/C; SizeArea_mm2: 1.28; SizeX_mm: 1.6; SizeY_mm: 0.8; SizeZ_mm: 1; EIA_Code: E24; U/M: EA; AEC Category: Q200; Green_Lifecycle: Active; Green_REACh: Passed
signal-integrity model Resistor
simulation model Resistor
footprint 0603
footprint 0603M
footprint 0603L
footprint 0603_HV
footprint 0603S
pins: 1, 2

## CRCW06032R21FKEA
designator R?  ValueDisplayed: 2.21  (hidden comment: CRCW06032R21FKEA)
RES, 2.21, 1%, 0.1 W, 0603; Manufacturer: Vishay-Dale; CompType: Resistor; Value: 2.21; Value_Code: 2R21; Tolerance_%: 1; Power_W: 0.1; Value2: 0.1W; VDC_V: 75; TempCo: 100 ppm/C; SizeArea_mm2: 1.28; SizeX_mm: 1.6; SizeY_mm: 0.8; EIA_Code: E96; U/M: EA; AEC Category: Q200; Green_Lifecycle: Active; Green_REACh: Passed
signal-integrity model Resistor
simulation model Resistor
footprint 0603
footprint 0603M
footprint 0603L
footprint 0603_HV
footprint 0603S
pins: 1, 2

## CRCW06032R26FKEA
designator R?  ValueDisplayed: 2.26  (hidden comment: CRCW06032R26FKEA)
RES, 2.26, 1%, 0.1 W, 0603; Manufacturer: Vishay-Dale; CompType: Resistor; Value: 2.26; Value_Code: 2R26; Tolerance_%: 1; Power_W: 0.1; Value2: 0.1W; VDC_V: 75; TempCo: 100 ppm/C; SizeArea_mm2: 1.28; SizeX_mm: 1.6; SizeY_mm: 0.8; EIA_Code: E96; U/M: EA; AEC Category: Q200
signal-integrity model Resistor
simulation model Resistor
footprint 0603
footprint 0603M
footprint 0603L
footprint 0603_HV
footprint 0603S
pins: 1, 2

## CRCW06032R32FKEA
designator R?  ValueDisplayed: 2.32  (hidden comment: CRCW06032R32FKEA)
RES, 2.32, 1%, 0.1 W, 0603; Manufacturer: Vishay-Dale; CompType: Resistor; Value: 2.32; Value_Code: 2R32; Tolerance_%: 1; Power_W: 0.1; Value2: 0.1W; VDC_V: 75; TempCo: 100 ppm/C; SizeArea_mm2: 1.28; SizeX_mm: 1.6; SizeY_mm: 0.8; EIA_Code: E96; U/M: EA; AEC Category: Q200
signal-integrity model Resistor
simulation model Resistor
footprint 0603
footprint 0603M
footprint 0603L
footprint 0603_HV
footprint 0603S
pins: 1, 2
